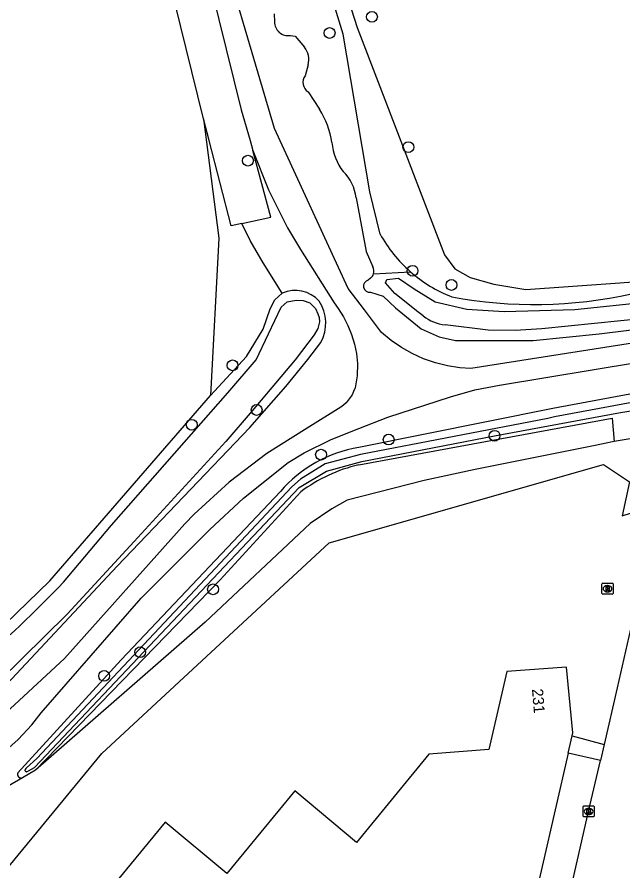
# Model space of a CAD drawing. Extents: x 161389 to 162585, y 388479 to 389761.
# Drawn here: x 162346.4 to 162401.2, y 389058.4 to 389135.6 of the extents above; entities that cross this region are included whole.
import ezdxf

# ---------------------------------------------------------------- set-up
doc = ezdxf.new("R2010")
doc.units = 0
for name, color, linetype in [('IMGEO_Berm_groen', 7, 'Continuous'), ('IMGEO_Boom', 7, 'Continuous'), ('IMGEO_Bouwland', 7, 'Continuous'), ('IMGEO_Grasland_overig', 7, 'Continuous'), ('IMGEO_Groenvoorziening', 7, 'Continuous'), ('IMGEO_Kolk', 7, 'Continuous'), ('IMGEO_Loofbos', 7, 'Continuous'), ('IMGEO_Pand', 7, 'Continuous'), ('IMGEO_Pand_nummerreeks', 7, 'Continuous'), ('IMGEO_Rijbaan_lokaal_gesloten', 7, 'Continuous'), ('IMGEO_Rioolput', 7, 'Continuous'), ('IMGEO_Waterloop', 7, 'Continuous')]:
    doc.layers.add(name, color=color, linetype=linetype)

msp = doc.modelspace()

# ---------------------------------------------------------------- linework, layer by layer
at = {"layer": 'IMGEO_Berm_groen'}
msp.add_lwpolyline([(162399.15, 389068.347), (162396.234, 389069.017)], dxfattribs=at)
at = {"layer": 'IMGEO_Boom'}
for centre in [(162378.512, 389135.577), (162374.685, 389134.116), (162381.801, 389123.799), (162367.306, 389122.576), (162382.182, 389112.62), (162385.696, 389111.341), (162365.917, 389104.074), (162368.093, 389100.039), (162362.222, 389098.703), (162380.021, 389097.364), (162389.587, 389097.707), (162373.91, 389096), (162364.149, 389083.828), (162357.566, 389078.143), (162354.31, 389076)]:
    msp.add_circle(centre, 0.489, dxfattribs=at)
at = {"layer": 'IMGEO_Bouwland'}
for points in [[(162358.496, 389209.229), (162358.875, 389207.257), (162364.791, 389176.538), (162367.643, 389161.523), (162369.563, 389152.424), (162370.495, 389148.102), (162371.166, 389145.669), (162371.753, 389144.747), (162372.466, 389144.118), (162373.976, 389142.943), (162374.437, 389142.356), (162375.063, 389141.201), (162377.181, 389134.613), (162385.056, 389114.051), (162385.992, 389112.809), (162387.376, 389112.012), (162389.515, 389111.425), (162392.409, 389110.921), (162400.482, 389111.487), (162407.087, 389111.977), (162424.682, 389114.172), (162440.911, 389116.066)], [(162309.854, 389056.722), (162310.421, 389057.053), (162326.326, 389065.495), (162334.102, 389070.683), (162343.361, 389078.749), (162349.4, 389084.605), (162363.917, 389101.34)]]:
    msp.add_lwpolyline(points, dxfattribs=at)
at = {"layer": 'IMGEO_Grasland_overig'}
for points in [[(162443.128, 389111.815), (162441.869, 389111.714), (162423.37, 389109.414), (162387.435, 389103.792), (162386.449, 389103.86), (162385.337, 389104.032), (162384.246, 389104.303), (162383.182, 389104.67), (162382.156, 389105.13), (162381.175, 389105.68), (162380.247, 389106.316), (162379.38, 389107.032), (162377.829, 389109.083), (162376.361, 389111.024), (162369.698, 389125.495), (162363.721, 389145.826)], [(162363.28, 389126.345), (162364.685, 389115.578), (162363.917, 389101.34)], [(162363.917, 389101.34), (162367.188, 389104.858), (162368.671, 389107.35), (162369.308, 389109.177), (162369.734, 389110.004), (162370.407, 389110.599)], [(162345.171, 389069.022), (162346.529, 389070.241), (162347.773, 389071.576), (162348.632, 389072.657), (162357.656, 389083.031), (162363.851, 389089.234), (162366.896, 389092.076), (162370.937, 389095.277), (162372.4, 389096.154), (162374.82, 389097.375), (162377.339, 389098.374), (162379.935, 389099.397), (162385.624, 389101.218), (162387.811, 389101.86), (162390.049, 389102.288), (162419.529, 389107.157), (162425.043, 389108), (162433.502, 389108.658), (162441.985, 389108.557)]]:
    msp.add_lwpolyline(points, dxfattribs=at)
at = {"layer": 'IMGEO_Groenvoorziening'}
for points in [[(162378.38, 389110.682), (162379.528, 389110.312), (162380.637, 389109.275), (162382.947, 389107.385), (162384.59, 389106.646), (162386.048, 389106.318), (162393.071, 389106.318), (162399.046, 389106.934), (162407.567, 389107.981), (162426.033, 389110.496), (162442.252, 389112.986)], [(162378.382, 389111.942), (162378.181, 389111.782)], [(162441.985, 389108.557), (162436.446, 389107.928), (162432.566, 389107.183), (162394.86, 389100.187), (162377.318, 389096.648)], [(162442.099, 389108.529), (162463.695, 389102.686), (162488.778, 389092.794), (162488.169, 389091.372), (162487.431, 389089.647), (162462.452, 389098.908), (162438.603, 389104.956), (162406.149, 389100.295), (162406.403, 389098.189), (162400.404, 389097.175)], [(162377.322, 389095.078), (162400.222, 389099.308), (162400.404, 389097.175)], [(162400.404, 389097.175), (162398.535, 389096.802), (162387.833, 389094.669), (162383.219, 389093.661), (162376.278, 389091.878), (162374.882, 389091.102), (162372.943, 389089.784), (162363.443, 389080.865), (162348.12, 389067.475)], [(162345.423, 389058.454), (162354.094, 389069), (162374.638, 389088.034), (162399.442, 389095.107), (162401.799, 389093.537), (162401.128, 389090.478), (162408.163, 389092.728)], [(162370.235, 389092.679), (162355.839, 389077.444), (162346.521, 389067.249)], [(162348.12, 389067.475), (162364.808, 389084.679), (162372.075, 389092.627)], [(162396.592, 389070.577), (162399.481, 389069.789)], [(162346.945, 389066.797), (162340.423, 389063.025)], [(162348.12, 389067.475), (162346.945, 389066.797)]]:
    msp.add_lwpolyline(points, dxfattribs=at)
for centre, radius, start, end in [((162377.838, 389112.598), 0.852, 309.64627, 343.42298), ((162390.29, 389122.015), 12.6, 228.76685, 248.72972), ((162378.309, 389111.237), 0.56, 103.18289, 277.32595), ((162393.205, 389150.057), 40.481, 259.34248, 282.51129), ((162379.267, 389084.866), 11.942, 99.39139, 139.1373), ((162380.41, 389081.625), 13.803, 102.92907, 127.14775), ((162346.811, 389067.096), 0.328, 152.24237, 294.09613)]:
    msp.add_arc(centre, radius, start, end, dxfattribs=at)
at = {"layer": 'IMGEO_Kolk'}
for p, q in [((162397.593, 389063.33), (162397.593, 389064.182)), ((162397.668, 389064.256), (162398.52, 389064.256)), ((162398.081, 389064.036), (162398.106, 389064.036)), ((162398.594, 389064.182), (162398.594, 389063.33)), ((162398.52, 389063.256), (162397.668, 389063.256)), ((162398.104, 389063.476), (162398.079, 389063.476))]:
    msp.add_line(p, q, dxfattribs=at)
for points in [[(162397.593, 389063.33), (162397.593, 389064.182)], [(162397.668, 389064.256), (162398.52, 389064.256)], [(162397.914, 389063.956), (162398.037, 389063.956), (162398.037, 389063.805), (162398.167, 389063.956), (162398.331, 389063.956), (162398.185, 389063.805), (162398.338, 389063.556), (162398.186, 389063.556), (162398.101, 389063.72), (162398.037, 389063.653), (162398.037, 389063.556), (162397.914, 389063.556), (162397.914, 389063.956)], [(162398.594, 389064.182), (162398.594, 389063.33)], [(162398.52, 389063.256), (162397.668, 389063.256)]]:
    msp.add_lwpolyline(points, dxfattribs=at)
for centre, start, end in [((162397.67, 389064.18), 91.55205, 178.44795), ((162397.67, 389064.18), 91.55205, 178.44795), ((162398.518, 389064.18), 1.55205, 88.44795), ((162398.518, 389064.18), 1.55205, 88.44795), ((162397.67, 389063.332), 181.55205, 268.44795), ((162397.67, 389063.332), 181.55205, 268.44795), ((162398.518, 389063.332), 271.55205, 358.44795), ((162398.518, 389063.332), 271.55205, 358.44795)]:
    msp.add_arc(centre, 0.0765, start, end, dxfattribs=at)
for centre, major_axis, ratio, start_param, end_param in [((162398.08, 389063.756), (-0.387, 0.002), 0.722429, 4.712389, 7.853982), ((162398.105, 389063.756), (-0.39, 0.002), 0.717154, 1.570796, 4.712389)]:
    msp.add_ellipse(centre, major_axis=major_axis, ratio=ratio, start_param=start_param, end_param=end_param, dxfattribs=at)
at = {"layer": 'IMGEO_Loofbos'}
for points in [[(162367.76, 389123.504), (162369.165, 389119.939), (162370.882, 389116.513), (162372.057, 389114.537), (162375.097, 389109.723), (162375.465, 389109.224), (162375.936, 389108.47), (162376.338, 389107.678), (162376.668, 389106.853), (162376.922, 389106.001), (162377.1, 389105.13), (162377.199, 389104.247), (162377.185, 389103.139), (162376.98, 389102.051), (162376.956, 389101.979), (162376.846, 389101.695), (162376.71, 389101.423), (162376.551, 389101.164), (162376.37, 389100.92), (162376.167, 389100.694), (162375.945, 389100.486), (162375.705, 389100.299), (162372.66, 389098.406), (162369.024, 389096.118), (162365.607, 389093.514), (162362.437, 389090.615), (162361.589, 389089.746), (162350.739, 389077.584), (162344.546, 389071.887)], [(162370.407, 389110.599), (162368.69, 389113.325), (162367.516, 389115.371), (162366.74, 389116.898)], [(162345.529, 389075.247), (162355.478, 389085.909), (162367.47, 389098.455), (162370.74, 389102.148), (162372.722, 389104.612), (162373.897, 389106.135)]]:
    msp.add_lwpolyline(points, dxfattribs=at)
for centre, radius, start, end in [((162371.573, 389107.924), 2.918, 42.08845, 113.55059), ((162370.721, 389107.876), 3.622, 331.27313, 33.58912)]:
    msp.add_arc(centre, radius, start, end, dxfattribs=at)
at = {"layer": 'IMGEO_Pand'}
for points in [[(162396.592, 389070.577), (162396.653, 389070.841), (162396.09, 389076.798), (162390.69, 389076.394), (162389.08, 389069.363), (162383.65, 389068.933), (162377.126, 389060.957), (162371.545, 389065.621), (162365.408, 389058.133), (162359.823, 389062.773), (162328.936, 389025.268), (162325.326, 389009.487)], [(162396.234, 389069.017), (162396.592, 389070.577)], [(162396.234, 389069.017), (162382.137, 389007.539)]]:
    msp.add_lwpolyline(points, dxfattribs=at)
at = {"layer": 'IMGEO_Rijbaan_lokaal_gesloten'}
for points in [[(162408.163, 389092.728), (162406.907, 389091.431), (162405.772, 389090.027), (162404.767, 389088.528), (162403.9, 389086.945), (162403.178, 389085.29), (162402.792, 389084.192), (162400.663, 389074.932), (162399.481, 389069.789)], [(162399.481, 389069.789), (162399.15, 389068.347)], [(162385.073, 389006.813), (162388.76, 389022.887), (162393.397, 389043.229), (162398.094, 389063.755), (162399.15, 389068.347)]]:
    msp.add_lwpolyline(points, dxfattribs=at)
at = {"layer": 'IMGEO_Rioolput'}
for p, q in [((162399.299, 389083.459), (162399.299, 389084.311)), ((162399.374, 389084.385), (162400.226, 389084.385)), ((162399.787, 389084.165), (162399.812, 389084.165)), ((162400.3, 389084.311), (162400.3, 389083.459)), ((162400.226, 389083.385), (162399.374, 389083.385)), ((162399.81, 389083.605), (162399.785, 389083.605))]:
    msp.add_line(p, q, dxfattribs=at)
for points in [[(162399.299, 389083.459), (162399.299, 389084.311)], [(162399.374, 389084.385), (162400.226, 389084.385)], [(162399.888, 389084.083), (162399.636, 389084.085), (162399.636, 389083.685)], [(162399.636, 389083.685), (162399.76, 389083.685), (162399.76, 389083.847), (162399.771, 389083.847)], [(162399.814, 389084.004), (162399.76, 389084.004), (162399.76, 389083.923)], [(162399.76, 389083.923), (162399.812, 389083.923)], [(162399.818, 389083.818), (162399.889, 389083.685), (162400.029, 389083.685), (162399.964, 389083.811)], [(162400.3, 389084.311), (162400.3, 389083.459)], [(162400.226, 389083.385), (162399.374, 389083.385)]]:
    msp.add_lwpolyline(points, dxfattribs=at)
for centre, radius, start, end in [((162399.376, 389084.309), 0.0765, 91.55205, 178.44795), ((162399.376, 389084.309), 0.0765, 91.55205, 178.44795), ((162399.77, 389083.794), 0.0533, 26.02933, 88.69889), ((162399.796, 389084.112), 0.19, 274.7715, 282.96867), ((162399.82, 389083.908), 0.0964, 77.00612, 93.18647), ((162399.834, 389083.965), 0.0378, 276.66336, 79.67722), ((162399.887, 389083.973), 0.109, 350.36119, 89.41601), ((162399.885, 389083.973), 0.112, 277.58423, 350.98172), ((162399.869, 389083.758), 0.108, 29.51342, 73.79051), ((162400.224, 389084.309), 0.0765, 1.55205, 88.44795), ((162400.224, 389084.309), 0.0765, 1.55205, 88.44795), ((162399.376, 389083.461), 0.0765, 181.55205, 268.44795), ((162399.376, 389083.461), 0.0765, 181.55205, 268.44795), ((162400.224, 389083.461), 0.0765, 271.55205, 358.44795), ((162400.224, 389083.461), 0.0765, 271.55205, 358.44795)]:
    msp.add_arc(centre, radius, start, end, dxfattribs=at)
for centre, major_axis, ratio, start_param, end_param in [((162399.786, 389083.885), (-0.387, 0.002), 0.722429, 4.712389, 7.853982), ((162399.811, 389083.885), (-0.39, 0.002), 0.717154, 1.570796, 4.712389)]:
    msp.add_ellipse(centre, major_axis=major_axis, ratio=ratio, start_param=start_param, end_param=end_param, dxfattribs=at)
at = {"layer": 'IMGEO_Waterloop'}
for points in [[(162351.035, 389207.23), (162353.933, 389193.193), (162355.692, 389183.231), (162360.391, 389154.094), (162361.996, 389146.213), (162366.679, 389127.181), (162367.496, 389124.404), (162367.76, 389123.504)], [(162363.28, 389126.345), (162358.58, 389145.445), (162356.947, 389153.466), (162352.241, 389182.648), (162350.495, 389192.535), (162348.174, 389203.928)], [(162379.246, 389115.942), (162378.33, 389119.744), (162375.906, 389134.011), (162374.73, 389137.872)], [(162369.689, 389135.837), (162369.708, 389135.137)], [(162371.147, 389133.895), (162371.571, 389133.827), (162372.425, 389132.834)], [(162372.743, 389131.252), (162372.462, 389130.252)], [(162372.741, 389128.792), (162373.779, 389127.231)], [(162366.74, 389116.898), (162365.776, 389116.697), (162363.814, 389124.392), (162363.28, 389126.345)], [(162366.74, 389116.898), (162369.36, 389117.47), (162367.76, 389123.504)], [(162377.07, 389119.226), (162377.997, 389114.352), (162378.594, 389112.983)], [(162383.153, 389108.541), (162382.667, 389108.924), (162380.577, 389110.569), (162379.734, 389111.533), (162379.857, 389111.821), (162380.925, 389111.944), (162382.321, 389110.999), (162384.21, 389109.808), (162387.085, 389109.151), (162390.452, 389108.946), (162396.859, 389109.11), (162405.771, 389110.055), (162419.57, 389111.533), (162427.126, 389112.683), (162461.5, 389118.638)], [(162461.5, 389118.638), (162461.715, 389117.19), (162445.144, 389114.275), (162431.746, 389111.934), (162423.948, 389110.794), (162405.761, 389108.576), (162393.877, 389107.375), (162391.454, 389107.211), (162388.998, 389107.246), (162385.114, 389107.724)], [(162378.655, 389112.355), (162381.985, 389112.54)], [(162350.648, 389084.466), (162354.977, 389089.632), (162365.484, 389101.593), (162368.05, 389104.571), (162369.169, 389106.923), (162370.319, 389109.346), (162370.843, 389109.829), (162371.674, 389109.962), (162372.29, 389109.932), (162372.886, 389109.726), (162373.399, 389109.223), (162373.609, 389108.743), (162373.753, 389108.404), (162373.784, 389108.004), (162373.625, 389107.408), (162373.286, 389106.823), (162371.576, 389104.575), (162367.675, 389099.954), (162365.313, 389097.203), (162357.039, 389088.15), (162350.981, 389081.577), (162342.814, 389073.576)], [(162486.958, 389092.675), (162463.45, 389101.946), (162442.207, 389107.406), (162440.715, 389107.629), (162436.563, 389107.158), (162432.71, 389106.418), (162395.008, 389099.423), (162394.401, 389099.278)], [(162347.36, 389067.365), (162347.462, 389067.423), (162348.025, 389067.712), (162371.925, 389093.029), (162374.412, 389094.498), (162377.586, 389095.388), (162389.587, 389097.707), (162400.959, 389099.822), (162405.34, 389100.503), (162424.166, 389103.514), (162438.645, 389105.748), (162462.684, 389099.652), (162486.213, 389090.928), (162486.356, 389090.894), (162486.503, 389090.864), (162486.565, 389090.853)], [(162394.401, 389099.278), (162377.479, 389096.001), (162374.293, 389095.17), (162372.064, 389093.778), (162371.262, 389093.088), (162348.231, 389068.546), (162347.308, 389067.704), (162347.228, 389067.619)]]:
    msp.add_lwpolyline(points, dxfattribs=at)
for centre, radius, start, end in [((162370.934, 389135.103), 1.226, 178.39994, 280.00515), ((162370.926, 389131.71), 1.874, 345.86307, 36.86821), ((162373.321, 389129.66), 1.044, 145.40995, 236.22716), ((162367.091, 389123.045), 7.89, 8.4797, 32.04554), ((162379.944, 389124.659), 5.069, 185.10777, 217.30671), ((162373.16, 389118.773), 3.937, 6.61459, 45.63856), ((162390.301, 389122.039), 12.625, 208.8776, 228.7985), ((162377.832, 389112.592), 0.857, 343.94001, 27.15589), ((162385.593, 389111.635), 3.94, 231.74172, 263.0227), ((162220.453, 389211.888), 182.173, 308.64536, 315.61667), ((162347.481, 389067.4), 0.334, 139.16119, 166.40659), ((162347.297, 389067.455), 0.143, 170.27065, 195.26978), ((162347.279, 389067.468), 0.13, 203.19104, 243.17235), ((162347.272, 389067.49), 0.147, 249.51232, 273.70183), ((162347.246, 389067.62), 0.279, 277.12461, 293.99841)]:
    msp.add_arc(centre, radius, start, end, dxfattribs=at)

# ---------------------------------------------------------------- texts
at = {"layer": 'IMGEO_Pand_nummerreeks'}
msp.add_text('231', height=1, rotation=274.85923, dxfattribs=at).set_placement((162392.967, 389074.805))

doc.saveas('drawing.dxf')
